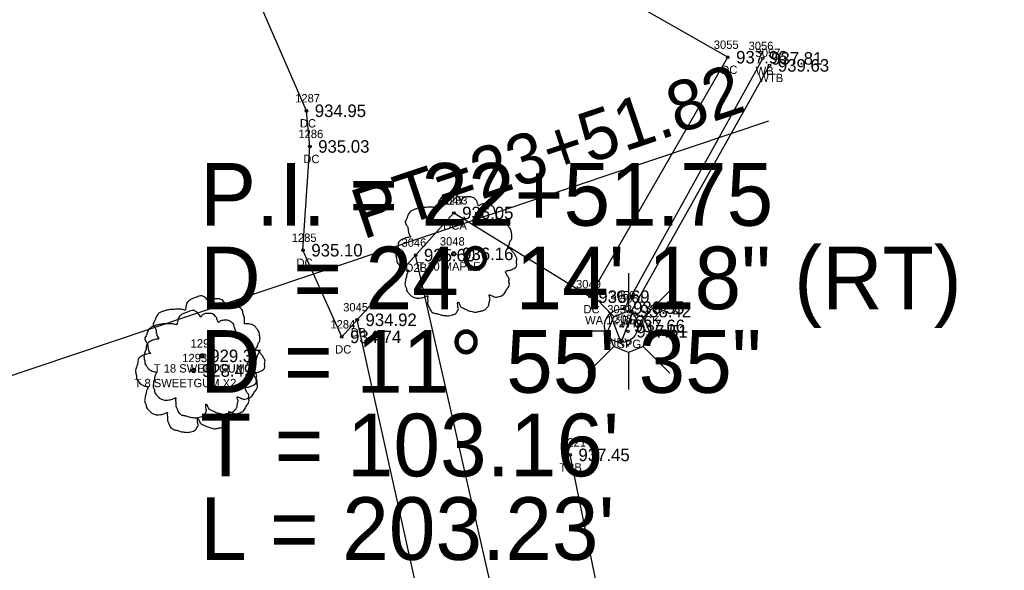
# Model space of a CAD drawing. Extents: x 1528109 to 1531398, y 1157799 to 1162548.
# Drawn here: x 1529933.4 to 1530051.3, y 1159470.8 to 1159536.7 of the extents above; entities that cross this region are included whole.
import ezdxf

# ---------------------------------------------------------------- set-up
doc = ezdxf.new("R2010")
doc.units = 0
for name, color, linetype in [('RD_EX_BldgApp', 7, 'Continuous'), ('RD_EX_BldgApp_txCode', 7, 'Continuous'), ('RD_EX_Conc', 7, 'Continuous'), ('RD_EX_Conc_txCode', 7, 'Continuous'), ('RD_EX_Driveway', 7, 'Continuous'), ('RD_EX_Driveway_txCode', 7, 'Continuous'), ('RD_EX_Misc', 7, 'Continuous'), ('RD_EX_Misc_txCode', 7, 'Continuous'), ('RD_EX_TX_BldgApp_ELEV', 7, 'Continuous'), ('RD_EX_TX_Conc_ELEV', 7, 'Continuous'), ('RD_EX_TX_Driveway_ELEV', 7, 'Continuous'), ('RD_EX_TX_Misc_ELEV', 7, 'Continuous'), ('RD_EX_TX_VEG_ELEV', 7, 'Continuous'), ('RD_EX_VEG', 7, 'Continuous'), ('RD_EX_VEG_txCode', 7, 'Continuous'), ('RD_HC_Cl', 7, 'Continuous'), ('RD_HC_Data', 7, 'Continuous'), ('RD_SMD_Locator', 7, 'Continuous')]:
    doc.layers.add(name, color=color, linetype=linetype)

msp = doc.modelspace()

# ---------------------------------------------------------------- linework, layer by layer
at = {"layer": 'RD_EX_BldgApp'}
for p, q in [((1530005.82, 1159502.19), (1530022.34, 1159532.03)), ((1530006.32, 1159501.83), (1530006.32, 1159506.34)), ((1530004.53, 1159501.13), (1530001.35, 1159504.31)), ((1530008.07, 1159501.06), (1530011.27, 1159504.25)), ((1530005.4, 1159498.02), (1530004.09, 1159501.5)), ((1530005.4, 1159498.02), (1530006.72, 1159501.46)), ((1530003.79, 1159499.37), (1529999.27, 1159499.37)), ((1530008.79, 1159499.28), (1530013.29, 1159499.28)), ((1530004.51, 1159497.55), (1530001.39, 1159494.44)), ((1530008.02, 1159497.53), (1530011.21, 1159494.34)), ((1530006.28, 1159496.82), (1530006.28, 1159492.41))]:
    msp.add_line(p, q, dxfattribs=at)
msp.add_lwpolyline([(1530004.53, 1159501.13), (1530006.32, 1159501.83), (1530008.07, 1159501.06), (1530008.79, 1159499.28), (1530008.02, 1159497.53), (1530006.28, 1159496.82), (1530004.51, 1159497.55), (1530003.79, 1159499.37)], close=True, dxfattribs=at)
for radius in [2, 0.15]:
    msp.add_circle((1530005.4, 1159500.01), radius, dxfattribs=at)
at = {"layer": 'RD_EX_Conc'}
for points in [[(1529985.36, 1159513.53), (1530001.66, 1159503.51), (1530018.15, 1159532.17), (1529971.46, 1159558.81), (1529963.8, 1159566.66), (1529958.86, 1159577.36), (1529958.23, 1159588.94), (1529961.99, 1159602.52), (1529972.79, 1159627.08)], [(1529985.36, 1159513.53), (1529971.94, 1159498.7), (1529967.31, 1159509.07), (1529968.13, 1159521.49), (1529967.72, 1159525.76), (1529959.91, 1159543.75), (1529949.2, 1159567.33), (1529946.42, 1159580.44), (1529949.32, 1159603.4)]]:
    msp.add_lwpolyline(points, dxfattribs=at)
at = {"layer": 'RD_EX_Driveway'}
for points in [[(1530203.32, 1159298.84), (1530163.28, 1159286.11), (1530119.04, 1159286.75), (1530073.38, 1159307.7), (1530032.71, 1159350.36), (1530014.21, 1159381.53), (1530002.1, 1159415.11), (1529980.79, 1159508.48)], [(1530206.82, 1159287.58), (1530162.29, 1159275.2), (1530116.93, 1159276.42), (1530063.08, 1159301.27), (1530024.72, 1159342.07), (1530004.76, 1159375.72), (1529993.09, 1159413.67), (1529973.79, 1159500.74)]]:
    msp.add_lwpolyline(points, dxfattribs=at)
at = {"layer": 'RD_EX_Misc'}
msp.add_line((1530006.63, 1159501.79), (1530023.15, 1159531.19), dxfattribs=at)
at = {"layer": 'RD_EX_VEG'}
msp.add_lwpolyline([(1530049.32, 1159334.73), (1530026.44, 1159368.44), (1530010.27, 1159430.9), (1529999.28, 1159484.57)], dxfattribs=at)
for centre, radius in [((1529985.36, 1159508.63), 0.25), ((1529985.35, 1159508.61), 0.0001), ((1529955.21, 1159496.42), 0.25), ((1529955.19, 1159496.4), 0.0001), ((1529954.21, 1159494.67), 0.25), ((1529954.19, 1159494.65), 0.0001)]:
    msp.add_circle(centre, radius, dxfattribs=at)
for points in [[(1529985.49, 1159515.79), (1529985.19, 1159515.82), (1529984.87, 1159515.72), (1529984.62, 1159515.62), (1529984.39, 1159515.54), (1529984.17, 1159515.44), (1529983.87, 1159515.27), (1529983.64, 1159515.07), (1529983.52, 1159514.82), (1529983.47, 1159514.59), (1529983.42, 1159514.32), (1529983.42, 1159514.14), (1529983.29, 1159514.12), (1529983.14, 1159514.14), (1529982.89, 1159514.22), (1529982.64, 1159514.22), (1529982.39, 1159514.22), (1529982.04, 1159514.19), (1529981.69, 1159514.19), (1529981.42, 1159514.14), (1529981.09, 1159514.09), (1529980.72, 1159513.97), (1529980.37, 1159513.84), (1529980.07, 1159513.59), (1529979.82, 1159513.12), (1529979.69, 1159512.77), (1529979.54, 1159512.52), (1529979.69, 1159512.07), (1529979.87, 1159511.72), (1529979.89, 1159511.52), (1529979.97, 1159511.09), (1529980.07, 1159510.87), (1529980.19, 1159510.67), (1529980.12, 1159510.64), (1529979.74, 1159510.59), (1529979.44, 1159510.49), (1529979.02, 1159510.27), (1529978.79, 1159510.05), (1529978.69, 1159509.72), (1529978.67, 1159509.37), (1529978.57, 1159509.17), (1529978.49, 1159508.9), (1529978.47, 1159508.82), (1529978.42, 1159508.5), (1529978.52, 1159508.05), (1529978.54, 1159507.7), (1529978.67, 1159507.47), (1529978.82, 1159507.3), (1529978.99, 1159507.05), (1529979.39, 1159506.82), (1529979.72, 1159506.72), (1529979.92, 1159506.7), (1529979.74, 1159506.2), (1529979.69, 1159505.85), (1529979.57, 1159505.45), (1529979.57, 1159505.37), (1529979.52, 1159504.9), (1529979.67, 1159504.57), (1529979.74, 1159504.2), (1529979.92, 1159503.97), (1529980.19, 1159503.67), (1529980.52, 1159503.45), (1529981.02, 1159503.32), (1529981.42, 1159503.35), (1529981.99, 1159503.52), (1529982.24, 1159503.6), (1529982.22, 1159503.42), (1529982.24, 1159503.05), (1529982.24, 1159502.62), (1529982.39, 1159502.3), (1529982.49, 1159502.02), (1529982.64, 1159501.77), (1529982.97, 1159501.55), (1529983.37, 1159501.47), (1529983.79, 1159501.32), (1529984.24, 1159501.25), (1529984.74, 1159501.22), (1529985.34, 1159501.37), (1529985.61, 1159501.5), (1529985.71, 1159501.67), (1529985.91, 1159502.05), (1529985.86, 1159502.27), (1529985.89, 1159502.87), (1529985.99, 1159502.7), (1529986.16, 1159502.35), (1529986.66, 1159502.05), (1529987.06, 1159501.87), (1529987.54, 1159501.72), (1529987.84, 1159501.65), (1529988.31, 1159501.72), (1529988.69, 1159501.8), (1529989.06, 1159501.92), (1529989.36, 1159502.2), (1529989.54, 1159502.47), (1529989.59, 1159502.75), (1529989.66, 1159503.12), (1529989.71, 1159503.3)], [(1529989.71, 1159503.3), (1529989.64, 1159503.47), (1529989.59, 1159503.72), (1529989.66, 1159503.7), (1529989.84, 1159503.65), (1529990.11, 1159503.52), (1529990.34, 1159503.45), (1529990.66, 1159503.47), (1529990.94, 1159503.57), (1529991.39, 1159503.85), (1529991.66, 1159504.32), (1529991.94, 1159504.72), (1529992.01, 1159505.05), (1529991.96, 1159505.27), (1529991.94, 1159505.77), (1529991.74, 1159506.02), (1529991.69, 1159506.15), (1529991.59, 1159506.55), (1529991.66, 1159506.6), (1529991.94, 1159506.65), (1529992.31, 1159506.77), (1529992.59, 1159506.9), (1529992.81, 1159507.07), (1529992.89, 1159507.3), (1529992.86, 1159507.7), (1529992.91, 1159508.1), (1529992.84, 1159508.25), (1529992.74, 1159508.4), (1529992.66, 1159508.6), (1529992.51, 1159508.75), (1529992.41, 1159508.9), (1529992.31, 1159509), (1529992.19, 1159509.15), (1529992.01, 1159509.27), (1529991.86, 1159509.32), (1529991.81, 1159509.47), (1529991.96, 1159509.67), (1529992.01, 1159509.77), (1529992.04, 1159510), (1529992.26, 1159510.34), (1529992.31, 1159510.74), (1529992.26, 1159511.17), (1529992.21, 1159511.44), (1529992.06, 1159511.72), (1529991.86, 1159511.97), (1529991.74, 1159512.14), (1529991.56, 1159512.27), (1529991.24, 1159512.39), (1529990.99, 1159512.44), (1529990.64, 1159512.44), (1529990.44, 1159512.49), (1529990.46, 1159512.54), (1529990.46, 1159512.69), (1529990.46, 1159512.97), (1529990.39, 1159513.42), (1529990.24, 1159513.92), (1529990.24, 1159513.94), (1529990.14, 1159514.19), (1529989.91, 1159514.39), (1529989.74, 1159514.49), (1529989.54, 1159514.62), (1529989.29, 1159514.64), (1529988.99, 1159514.64), (1529988.71, 1159514.59), (1529988.51, 1159514.49), (1529988.34, 1159514.37), (1529988.26, 1159514.52), (1529988.16, 1159514.82), (1529988.11, 1159514.97), (1529987.96, 1159515.14), (1529987.74, 1159515.34), (1529987.29, 1159515.47), (1529986.66, 1159515.39), (1529986.36, 1159515.19), (1529986.21, 1159515.02), (1529986.16, 1159515.14), (1529985.96, 1159515.34), (1529985.86, 1159515.52), (1529985.69, 1159515.64), (1529985.54, 1159515.74), (1529985.44, 1159515.79)], [(1529955.34, 1159503.58), (1529955.04, 1159503.61), (1529954.71, 1159503.51), (1529954.46, 1159503.41), (1529954.24, 1159503.33), (1529954.01, 1159503.23), (1529953.71, 1159503.06), (1529953.49, 1159502.86), (1529953.36, 1159502.61), (1529953.31, 1159502.38), (1529953.26, 1159502.11), (1529953.26, 1159501.93), (1529953.14, 1159501.91), (1529952.99, 1159501.93), (1529952.74, 1159502.01), (1529952.49, 1159502.01), (1529952.24, 1159502.01), (1529951.89, 1159501.98), (1529951.54, 1159501.98), (1529951.27, 1159501.93), (1529950.94, 1159501.88), (1529950.57, 1159501.76), (1529950.22, 1159501.63), (1529949.92, 1159501.38), (1529949.67, 1159500.91), (1529949.54, 1159500.56), (1529949.39, 1159500.31), (1529949.54, 1159499.86), (1529949.72, 1159499.51), (1529949.74, 1159499.31), (1529949.82, 1159498.89), (1529949.92, 1159498.66), (1529950.04, 1159498.46), (1529949.97, 1159498.44), (1529949.59, 1159498.39), (1529949.29, 1159498.29), (1529948.87, 1159498.06), (1529948.64, 1159497.84), (1529948.54, 1159497.51), (1529948.52, 1159497.16), (1529948.42, 1159496.96), (1529948.34, 1159496.69), (1529948.32, 1159496.61), (1529948.27, 1159496.29), (1529948.37, 1159495.84), (1529948.39, 1159495.49), (1529948.52, 1159495.26), (1529948.67, 1159495.09), (1529948.84, 1159494.84), (1529949.24, 1159494.61), (1529949.57, 1159494.51), (1529949.77, 1159494.49), (1529949.59, 1159493.99), (1529949.54, 1159493.64), (1529949.42, 1159493.24), (1529949.42, 1159493.16), (1529949.37, 1159492.69), (1529949.52, 1159492.36), (1529949.59, 1159491.99), (1529949.77, 1159491.76), (1529950.04, 1159491.46), (1529950.37, 1159491.24), (1529950.87, 1159491.11), (1529951.27, 1159491.14), (1529951.84, 1159491.31), (1529952.09, 1159491.39), (1529952.06, 1159491.21), (1529952.09, 1159490.84), (1529952.09, 1159490.41), (1529952.24, 1159490.09), (1529952.34, 1159489.81), (1529952.49, 1159489.56), (1529952.81, 1159489.34), (1529953.21, 1159489.26), (1529953.64, 1159489.11), (1529954.09, 1159489.04), (1529954.59, 1159489.01), (1529955.19, 1159489.16), (1529955.46, 1159489.29), (1529955.56, 1159489.46), (1529955.76, 1159489.84), (1529955.71, 1159490.06), (1529955.74, 1159490.66), (1529955.84, 1159490.49), (1529956.01, 1159490.14), (1529956.51, 1159489.84), (1529956.91, 1159489.66), (1529957.39, 1159489.51), (1529957.69, 1159489.44), (1529958.16, 1159489.51), (1529958.54, 1159489.59), (1529958.91, 1159489.71), (1529959.21, 1159489.99), (1529959.39, 1159490.26), (1529959.44, 1159490.54), (1529959.51, 1159490.91), (1529959.56, 1159491.09)], [(1529959.56, 1159491.09), (1529959.49, 1159491.26), (1529959.44, 1159491.51), (1529959.51, 1159491.49), (1529959.69, 1159491.44), (1529959.96, 1159491.31), (1529960.19, 1159491.24), (1529960.51, 1159491.26), (1529960.79, 1159491.36), (1529961.24, 1159491.64), (1529961.51, 1159492.11), (1529961.79, 1159492.51), (1529961.86, 1159492.84), (1529961.81, 1159493.06), (1529961.79, 1159493.56), (1529961.59, 1159493.81), (1529961.54, 1159493.94), (1529961.44, 1159494.34), (1529961.51, 1159494.39), (1529961.79, 1159494.44), (1529962.16, 1159494.56), (1529962.44, 1159494.69), (1529962.66, 1159494.86), (1529962.74, 1159495.09), (1529962.71, 1159495.49), (1529962.76, 1159495.89), (1529962.69, 1159496.04), (1529962.59, 1159496.19), (1529962.51, 1159496.39), (1529962.36, 1159496.54), (1529962.26, 1159496.69), (1529962.16, 1159496.79), (1529962.04, 1159496.94), (1529961.86, 1159497.06), (1529961.71, 1159497.11), (1529961.66, 1159497.26), (1529961.81, 1159497.46), (1529961.86, 1159497.56), (1529961.89, 1159497.79), (1529962.11, 1159498.14), (1529962.16, 1159498.54), (1529962.11, 1159498.96), (1529962.06, 1159499.24), (1529961.91, 1159499.51), (1529961.71, 1159499.76), (1529961.59, 1159499.94), (1529961.41, 1159500.06), (1529961.09, 1159500.19), (1529960.84, 1159500.24), (1529960.49, 1159500.24), (1529960.29, 1159500.29), (1529960.31, 1159500.34), (1529960.31, 1159500.48), (1529960.31, 1159500.76), (1529960.24, 1159501.21), (1529960.09, 1159501.71), (1529960.09, 1159501.73), (1529959.99, 1159501.98), (1529959.76, 1159502.18), (1529959.59, 1159502.28), (1529959.39, 1159502.41), (1529959.14, 1159502.43), (1529958.84, 1159502.43), (1529958.56, 1159502.38), (1529958.36, 1159502.28), (1529958.19, 1159502.16), (1529958.11, 1159502.31), (1529958.01, 1159502.61), (1529957.96, 1159502.76), (1529957.81, 1159502.93), (1529957.59, 1159503.13), (1529957.14, 1159503.26), (1529956.51, 1159503.18), (1529956.21, 1159502.98), (1529956.06, 1159502.81), (1529956.01, 1159502.93), (1529955.81, 1159503.13), (1529955.71, 1159503.31), (1529955.54, 1159503.43), (1529955.39, 1159503.53), (1529955.29, 1159503.58)], [(1529954.34, 1159501.84), (1529954.04, 1159501.86), (1529953.71, 1159501.76), (1529953.46, 1159501.66), (1529953.24, 1159501.59), (1529953.01, 1159501.49), (1529952.71, 1159501.31), (1529952.49, 1159501.11), (1529952.36, 1159500.86), (1529952.31, 1159500.64), (1529952.26, 1159500.36), (1529952.26, 1159500.19), (1529952.14, 1159500.16), (1529951.99, 1159500.19), (1529951.74, 1159500.26), (1529951.49, 1159500.26), (1529951.24, 1159500.26), (1529950.89, 1159500.24), (1529950.54, 1159500.24), (1529950.26, 1159500.19), (1529949.94, 1159500.14), (1529949.56, 1159500.01), (1529949.21, 1159499.89), (1529948.91, 1159499.64), (1529948.66, 1159499.17), (1529948.54, 1159498.82), (1529948.39, 1159498.57), (1529948.54, 1159498.12), (1529948.71, 1159497.77), (1529948.74, 1159497.57), (1529948.81, 1159497.14), (1529948.91, 1159496.92), (1529949.04, 1159496.72), (1529948.96, 1159496.69), (1529948.59, 1159496.64), (1529948.29, 1159496.54), (1529947.86, 1159496.32), (1529947.64, 1159496.09), (1529947.54, 1159495.77), (1529947.51, 1159495.42), (1529947.42, 1159495.22), (1529947.34, 1159494.94), (1529947.32, 1159494.87), (1529947.27, 1159494.54), (1529947.37, 1159494.09), (1529947.39, 1159493.74), (1529947.51, 1159493.52), (1529947.66, 1159493.34), (1529947.84, 1159493.09), (1529948.24, 1159492.87), (1529948.56, 1159492.77), (1529948.76, 1159492.74), (1529948.59, 1159492.24), (1529948.54, 1159491.89), (1529948.41, 1159491.49), (1529948.41, 1159491.42), (1529948.36, 1159490.94), (1529948.51, 1159490.62), (1529948.59, 1159490.24), (1529948.76, 1159490.02), (1529949.04, 1159489.72), (1529949.36, 1159489.49), (1529949.86, 1159489.37), (1529950.26, 1159489.39), (1529950.84, 1159489.57), (1529951.09, 1159489.64), (1529951.06, 1159489.47), (1529951.09, 1159489.09), (1529951.09, 1159488.67), (1529951.24, 1159488.34), (1529951.34, 1159488.07), (1529951.49, 1159487.82), (1529951.81, 1159487.6), (1529952.21, 1159487.52), (1529952.64, 1159487.37), (1529953.09, 1159487.3), (1529953.59, 1159487.27), (1529954.19, 1159487.42), (1529954.46, 1159487.55), (1529954.56, 1159487.72), (1529954.76, 1159488.09), (1529954.71, 1159488.32), (1529954.74, 1159488.92), (1529954.84, 1159488.74), (1529955.01, 1159488.39), (1529955.51, 1159488.09), (1529955.91, 1159487.92), (1529956.39, 1159487.77), (1529956.69, 1159487.7), (1529957.16, 1159487.77), (1529957.54, 1159487.84), (1529957.91, 1159487.97), (1529958.21, 1159488.24), (1529958.39, 1159488.52), (1529958.44, 1159488.79), (1529958.51, 1159489.17), (1529958.56, 1159489.34)], [(1529958.56, 1159489.34), (1529958.49, 1159489.52), (1529958.44, 1159489.77), (1529958.51, 1159489.74), (1529958.69, 1159489.69), (1529958.96, 1159489.57), (1529959.18, 1159489.49), (1529959.51, 1159489.52), (1529959.78, 1159489.62), (1529960.23, 1159489.89), (1529960.51, 1159490.37), (1529960.78, 1159490.77), (1529960.86, 1159491.09), (1529960.81, 1159491.32), (1529960.78, 1159491.82), (1529960.58, 1159492.07), (1529960.53, 1159492.19), (1529960.43, 1159492.59), (1529960.51, 1159492.64), (1529960.78, 1159492.69), (1529961.16, 1159492.82), (1529961.43, 1159492.94), (1529961.66, 1159493.12), (1529961.73, 1159493.34), (1529961.71, 1159493.74), (1529961.76, 1159494.14), (1529961.68, 1159494.29), (1529961.58, 1159494.44), (1529961.51, 1159494.64), (1529961.36, 1159494.79), (1529961.26, 1159494.94), (1529961.16, 1159495.04), (1529961.03, 1159495.19), (1529960.86, 1159495.32), (1529960.71, 1159495.37), (1529960.66, 1159495.52), (1529960.81, 1159495.72), (1529960.86, 1159495.82), (1529960.88, 1159496.04), (1529961.11, 1159496.39), (1529961.16, 1159496.79), (1529961.11, 1159497.22), (1529961.06, 1159497.49), (1529960.91, 1159497.77), (1529960.71, 1159498.02), (1529960.58, 1159498.19), (1529960.41, 1159498.32), (1529960.08, 1159498.44), (1529959.83, 1159498.49), (1529959.48, 1159498.49), (1529959.28, 1159498.54), (1529959.31, 1159498.59), (1529959.31, 1159498.74), (1529959.31, 1159499.02), (1529959.23, 1159499.46), (1529959.08, 1159499.96), (1529959.08, 1159499.99), (1529958.98, 1159500.24), (1529958.76, 1159500.44), (1529958.59, 1159500.54), (1529958.39, 1159500.66), (1529958.14, 1159500.69), (1529957.84, 1159500.69), (1529957.56, 1159500.64), (1529957.36, 1159500.54), (1529957.19, 1159500.41), (1529957.11, 1159500.56), (1529957.01, 1159500.86), (1529956.96, 1159501.01), (1529956.81, 1159501.19), (1529956.59, 1159501.39), (1529956.14, 1159501.51), (1529955.51, 1159501.44), (1529955.21, 1159501.24), (1529955.06, 1159501.06), (1529955.01, 1159501.19), (1529954.81, 1159501.39), (1529954.71, 1159501.56), (1529954.54, 1159501.69), (1529954.39, 1159501.79), (1529954.29, 1159501.84)]]:
    msp.add_spline(points, degree=3, dxfattribs=at)
at = {"layer": 'RD_HC_Cl'}
msp.add_arc((1530368.9, 1159640.71), 480.41, 198.568, 222.8065, dxfattribs=at)
at = {"layer": 'RD_HC_Data'}
msp.add_line((1529913.5, 1159487.74), (1530023.07, 1159524.55), dxfattribs=at)
at = {"layer": 'RD_SMD_Locator'}
for centre in [(1530018.15, 1159532.17), (1530022.34, 1159532.03), (1530023.15, 1159531.19), (1529967.72, 1159525.76), (1529968.13, 1159521.49), (1529985.36, 1159513.53), (1529985.36, 1159513.53), (1529967.31, 1159509.07), (1529980.79, 1159508.48), (1529985.36, 1159508.63), (1530001.66, 1159503.51), (1530005.82, 1159502.19), (1530006.63, 1159501.79), (1529973.79, 1159500.74), (1530006.21, 1159499.36), (1529971.94, 1159498.7), (1529955.21, 1159496.42), (1529954.21, 1159494.67), (1529999.28, 1159484.57)]:
    msp.add_circle(centre, 0.15, dxfattribs=at)

# ---------------------------------------------------------------- texts
at = {"layer": 'RD_EX_BldgApp_txCode'}
for s, p in [('3052', (1530004.54, 1159500.36)), ('SPG', (1530004.95, 1159497.36))]:
    msp.add_text(s, height=1, dxfattribs=at).set_placement(p)
at = {"layer": 'RD_EX_Conc_txCode'}
for s, p in [('3055', (1530016.48, 1159533.17)), ('DC', (1530017.37, 1159530.17)), ('1287', (1529966.37, 1159526.76)), ('DC', (1529966.94, 1159523.76)), ('1286', (1529966.76, 1159522.49)), ('DC', (1529967.35, 1159519.49)), ('3047', (1529983.69, 1159514.53)), ('1283', (1529984.02, 1159514.53)), ('DCA', (1529984.09, 1159511.53)), ('DCA', (1529984.09, 1159511.53)), ('1285', (1529965.96, 1159510.07)), ('DC', (1529966.53, 1159507.07)), ('3049', (1529999.99, 1159504.51)), ('DC', (1530000.88, 1159501.51)), ('1284', (1529970.59, 1159499.7)), ('DC', (1529971.16, 1159496.7))]:
    msp.add_text(s, height=1, dxfattribs=at).set_placement(p)
at = {"layer": 'RD_EX_Driveway_txCode'}
for s, p in [('3046', (1529979.1, 1159509.48)), ('D2B', (1529979.56, 1159506.48)), ('3045', (1529972.12, 1159501.74)), ('DB', (1529973.01, 1159498.74))]:
    msp.add_text(s, height=1, dxfattribs=at).set_placement(p)
at = {"layer": 'RD_EX_Misc_txCode'}
for s, p in [('3056', (1530020.64, 1159533.03)), ('3057', (1530021.48, 1159532.19)), ('WB', (1530021.49, 1159530.03)), ('WTB', (1530021.82, 1159529.19)), ('3050', (1530004.11, 1159503.19)), ('3051', (1530005.25, 1159502.79)), ('3053', (1530003.73, 1159501.51)), ('WA 12 BLOCK', (1530001.08, 1159500.19)), ('WTA', (1530005.29, 1159499.79)), ('IRV', (1530004.44, 1159497.51))]:
    msp.add_text(s, height=1, dxfattribs=at).set_placement(p)
at = {"layer": 'RD_EX_TX_BldgApp_ELEV'}
msp.add_text('937.51', height=1.5, dxfattribs=at).set_placement((1530007.21, 1159498.61))
at = {"layer": 'RD_EX_TX_Conc_ELEV'}
for s, p in [('937.96', (1530019.15, 1159531.42)), ('934.95', (1529968.72, 1159525.01)), ('935.03', (1529969.13, 1159520.74)), ('936.05', (1529986.36, 1159512.78)), ('936.05', (1529986.36, 1159512.78)), ('935.10', (1529968.31, 1159508.32)), ('936.69', (1530002.66, 1159502.76)), ('934.74', (1529972.94, 1159497.95))]:
    msp.add_text(s, height=1.5, dxfattribs=at).set_placement(p)
at = {"layer": 'RD_EX_TX_Driveway_ELEV'}
for s, p in [('935.60', (1529981.79, 1159507.73)), ('934.92', (1529974.79, 1159499.99))]:
    msp.add_text(s, height=1.5, dxfattribs=at).set_placement(p)
at = {"layer": 'RD_EX_TX_Misc_ELEV'}
for s, p in [('937.81', (1530023.34, 1159531.28)), ('939.63', (1530024.15, 1159530.44)), ('936.55', (1530006.82, 1159501.44)), ('938.42', (1530007.63, 1159501.04)), ('937.66', (1530006.9, 1159499.26))]:
    msp.add_text(s, height=1.5, dxfattribs=at).set_placement(p)
at = {"layer": 'RD_EX_TX_VEG_ELEV'}
for s, p in [('936.16', (1529986.36, 1159507.88)), ('929.37', (1529956.21, 1159495.67)), ('928.49', (1529955.21, 1159493.92)), ('937.45', (1530000.28, 1159483.82))]:
    msp.add_text(s, height=1.5, dxfattribs=at).set_placement(p)
at = {"layer": 'RD_EX_VEG_txCode'}
for s, p in [('3048', (1529983.69, 1159509.63)), ('T 10 MAPLE', (1529980.99, 1159506.63)), ('1292', (1529953.86, 1159497.42)), ('1293', (1529952.86, 1159495.67)), ('T 18 SWEETGUM', (1529949.45, 1159494.42)), ('T 8 SWEETGUM X2', (1529947.15, 1159492.67)), ('1221', (1529998.21, 1159485.57)), ('TRB', (1529998.01, 1159482.57))]:
    msp.add_text(s, height=1, dxfattribs=at).set_placement(p)
at = {"layer": 'RD_HC_Data'}
msp.add_text('PT=23+51.82', height=6, rotation=18.568, dxfattribs=at).set_placement((1529974.47, 1159510.33))
for s, p in [('P.I. = 22+51.75', (1529955, 1159512)), ('D', (1529955, 1159502)), ('    = 24%%d 14\' 18" (RT)', (1529955, 1159502)), ('D = 11%%d 55\' 35"', (1529955, 1159492)), ("T = 103.16'", (1529955, 1159482)), ("L = 203.23'", (1529955, 1159472))]:
    msp.add_text(s, height=7.5, dxfattribs=at).set_placement(p)

doc.saveas('drawing.dxf')
